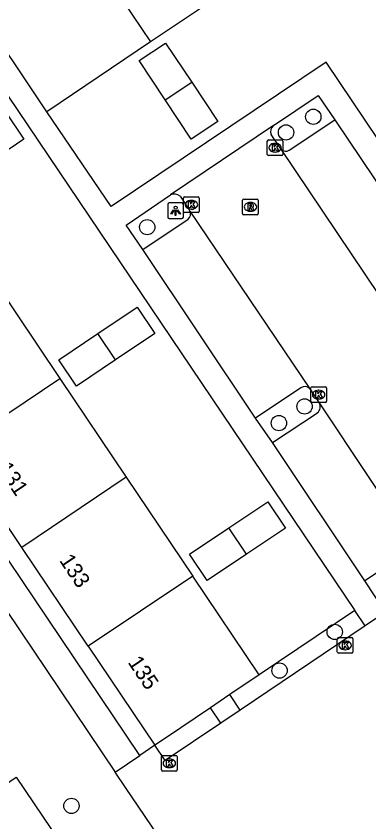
# Model space of a CAD drawing. Extents: x 158797 to 159887, y 384318 to 385255.
# Drawn here: x 159193.3 to 159215.9, y 384585.2 to 384636.8 of the extents above; entities that cross this region are included whole.
import ezdxf

# ---------------------------------------------------------------- set-up
doc = ezdxf.new("R2010")
doc.units = 0
for name, color, linetype in [('IMGEO_Boom', 7, 'Continuous'), ('IMGEO_Groenvoorziening', 7, 'Continuous'), ('IMGEO_Kolk', 7, 'Continuous'), ('IMGEO_Lichtpunt', 7, 'Continuous'), ('IMGEO_Pand', 7, 'Continuous'), ('IMGEO_Pand_nummerreeks', 7, 'Continuous'), ('IMGEO_Parkeervlak_open', 7, 'Continuous'), ('IMGEO_Rijbaan_lokaal_open', 7, 'Continuous'), ('IMGEO_Rioolput', 7, 'Continuous'), ('IMGEO_Voetpad_gesloten', 7, 'Continuous'), ('IMGEO_Voetpad_open', 7, 'Continuous')]:
    doc.layers.add(name, color=color, linetype=linetype)

msp = doc.modelspace()

# ---------------------------------------------------------------- linework, layer by layer
at = {"layer": 'IMGEO_Boom'}
for centre in [(159212.336, 384630.339), (159210.593, 384629.335), (159201.717, 384623.279), (159211.781, 384611.814), (159210.14, 384610.751), (159213.705, 384597.396), (159210.177, 384594.923), (159196.875, 384586.273)]:
    msp.add_circle(centre, 0.489, dxfattribs=at)
at = {"layer": 'IMGEO_Groenvoorziening'}
msp.add_lwpolyline([(159214.996, 384598.764), (159208.877, 384594.644)], dxfattribs=at)
at = {"layer": 'IMGEO_Kolk'}
for p, q in [((159209.397, 384627.93), (159209.397, 384628.782)), ((159209.472, 384628.856), (159210.324, 384628.856)), ((159209.885, 384628.636), (159209.91, 384628.636)), ((159210.398, 384628.782), (159210.398, 384627.93)), ((159209.908, 384628.076), (159209.883, 384628.076)), ((159210.324, 384627.856), (159209.472, 384627.856)), ((159204.046, 384624.284), (159204.046, 384625.136)), ((159204.121, 384625.21), (159204.973, 384625.21)), ((159204.534, 384624.99), (159204.559, 384624.99)), ((159205.047, 384625.136), (159205.047, 384624.284)), ((159204.557, 384624.43), (159204.532, 384624.43)), ((159204.973, 384624.21), (159204.121, 384624.21)), ((159212.181, 384612.145), (159212.181, 384612.997)), ((159212.256, 384613.071), (159213.108, 384613.071)), ((159213.182, 384612.997), (159213.182, 384612.145)), ((159212.669, 384612.851), (159212.694, 384612.851)), ((159213.108, 384612.071), (159212.256, 384612.071)), ((159212.692, 384612.291), (159212.667, 384612.291)), ((159213.948, 384597.035), (159214.8, 384597.035)), ((159213.873, 384596.109), (159213.873, 384596.961)), ((159214.361, 384596.815), (159214.386, 384596.815)), ((159214.874, 384596.961), (159214.874, 384596.109)), ((159214.8, 384596.035), (159213.948, 384596.035)), ((159214.384, 384596.255), (159214.359, 384596.255)), ((159202.632, 384588.57), (159202.632, 384589.422)), ((159202.707, 384589.496), (159203.559, 384589.496)), ((159203.12, 384589.276), (159203.145, 384589.276)), ((159203.633, 384589.422), (159203.633, 384588.57)), ((159203.559, 384588.496), (159202.707, 384588.496)), ((159203.143, 384588.716), (159203.118, 384588.716))]:
    msp.add_line(p, q, dxfattribs=at)
for points in [[(159209.397, 384627.93), (159209.397, 384628.782)], [(159209.472, 384628.856), (159210.324, 384628.856)], [(159209.718, 384628.556), (159209.841, 384628.556), (159209.841, 384628.405), (159209.971, 384628.556), (159210.135, 384628.556), (159209.989, 384628.405), (159210.142, 384628.156), (159209.99, 384628.156), (159209.905, 384628.32), (159209.841, 384628.253), (159209.841, 384628.156), (159209.718, 384628.156), (159209.718, 384628.556)], [(159210.398, 384628.782), (159210.398, 384627.93)], [(159210.324, 384627.856), (159209.472, 384627.856)], [(159204.046, 384624.284), (159204.046, 384625.136)], [(159204.121, 384625.21), (159204.973, 384625.21)], [(159204.367, 384624.91), (159204.49, 384624.91), (159204.49, 384624.759), (159204.62, 384624.91), (159204.784, 384624.91), (159204.638, 384624.759), (159204.791, 384624.51), (159204.639, 384624.51), (159204.554, 384624.674), (159204.49, 384624.607), (159204.49, 384624.51), (159204.367, 384624.51), (159204.367, 384624.91)], [(159205.047, 384625.136), (159205.047, 384624.284)], [(159204.973, 384624.21), (159204.121, 384624.21)], [(159212.181, 384612.145), (159212.181, 384612.997)], [(159212.256, 384613.071), (159213.108, 384613.071)], [(159213.182, 384612.997), (159213.182, 384612.145)], [(159212.502, 384612.771), (159212.625, 384612.771), (159212.625, 384612.62), (159212.755, 384612.771), (159212.919, 384612.771), (159212.773, 384612.62), (159212.926, 384612.371), (159212.774, 384612.371), (159212.689, 384612.535), (159212.625, 384612.468), (159212.625, 384612.371), (159212.502, 384612.371), (159212.502, 384612.771)], [(159213.108, 384612.071), (159212.256, 384612.071)], [(159213.948, 384597.035), (159214.8, 384597.035)], [(159213.873, 384596.109), (159213.873, 384596.961)], [(159214.194, 384596.735), (159214.317, 384596.735), (159214.317, 384596.584), (159214.447, 384596.735), (159214.611, 384596.735), (159214.465, 384596.584), (159214.618, 384596.335), (159214.466, 384596.335), (159214.381, 384596.499), (159214.317, 384596.432), (159214.317, 384596.335), (159214.194, 384596.335), (159214.194, 384596.735)], [(159214.874, 384596.961), (159214.874, 384596.109)], [(159214.8, 384596.035), (159213.948, 384596.035)], [(159202.632, 384588.57), (159202.632, 384589.422)], [(159202.707, 384589.496), (159203.559, 384589.496)], [(159203.633, 384589.422), (159203.633, 384588.57)], [(159202.953, 384589.196), (159203.076, 384589.196), (159203.076, 384589.045), (159203.206, 384589.196), (159203.37, 384589.196), (159203.224, 384589.045), (159203.377, 384588.796), (159203.225, 384588.796), (159203.14, 384588.96), (159203.076, 384588.893), (159203.076, 384588.796), (159202.953, 384588.796), (159202.953, 384589.196)], [(159203.559, 384588.496), (159202.707, 384588.496)]]:
    msp.add_lwpolyline(points, dxfattribs=at)
for centre, start, end in [((159209.474, 384628.78), 91.552, 178.448), ((159209.474, 384628.78), 91.552, 178.448), ((159210.322, 384628.78), 1.552, 88.448), ((159210.322, 384628.78), 1.552, 88.448), ((159209.474, 384627.932), 181.552, 268.448), ((159209.474, 384627.932), 181.552, 268.448), ((159210.322, 384627.932), 271.552, 358.448), ((159210.322, 384627.932), 271.552, 358.448), ((159204.123, 384625.134), 91.552, 178.448), ((159204.123, 384625.134), 91.552, 178.448), ((159204.971, 384625.134), 1.552, 88.448), ((159204.971, 384625.134), 1.552, 88.448), ((159204.123, 384624.286), 181.552, 268.448), ((159204.123, 384624.286), 181.552, 268.448), ((159204.971, 384624.286), 271.552, 358.448), ((159204.971, 384624.286), 271.552, 358.448), ((159212.258, 384612.995), 91.552, 178.448), ((159212.258, 384612.995), 91.552, 178.448), ((159213.106, 384612.995), 1.552, 88.448), ((159213.106, 384612.995), 1.552, 88.448), ((159212.258, 384612.147), 181.552, 268.448), ((159212.258, 384612.147), 181.552, 268.448), ((159213.106, 384612.147), 271.552, 358.448), ((159213.106, 384612.147), 271.552, 358.448), ((159213.95, 384596.959), 91.552, 178.448), ((159213.95, 384596.959), 91.552, 178.448), ((159214.798, 384596.959), 1.552, 88.448), ((159214.798, 384596.959), 1.552, 88.448), ((159213.95, 384596.111), 181.552, 268.448), ((159213.95, 384596.111), 181.552, 268.448), ((159214.798, 384596.111), 271.552, 358.448), ((159214.798, 384596.111), 271.552, 358.448), ((159202.709, 384589.42), 91.552, 178.448), ((159202.709, 384589.42), 91.552, 178.448), ((159203.557, 384589.42), 1.552, 88.448), ((159203.557, 384589.42), 1.552, 88.448), ((159202.709, 384588.572), 181.552, 268.448), ((159202.709, 384588.572), 181.552, 268.448), ((159203.557, 384588.572), 271.552, 358.448), ((159203.557, 384588.572), 271.552, 358.448)]:
    msp.add_arc(centre, 0.0765, start, end, dxfattribs=at)
for centre, major_axis, ratio, start_param, end_param in [((159209.884, 384628.356), (-0.387, 0.002), 0.722429, 4.712389, 7.853982), ((159209.909, 384628.356), (-0.39, 0.002), 0.717154, 1.570796, 4.712389), ((159204.533, 384624.71), (-0.387, 0.002), 0.722429, 4.712389, 7.853982), ((159204.558, 384624.71), (-0.39, 0.002), 0.717154, 1.570796, 4.712389), ((159212.668, 384612.571), (-0.387, 0.002), 0.722429, 4.712389, 7.853982), ((159212.693, 384612.571), (-0.39, 0.002), 0.717154, 1.570796, 4.712389), ((159214.36, 384596.535), (-0.387, 0.002), 0.722429, 4.712389, 7.853982), ((159214.385, 384596.535), (-0.39, 0.002), 0.717154, 1.570796, 4.712389), ((159203.119, 384588.996), (-0.387, 0.002), 0.722429, 4.712389, 7.853982), ((159203.144, 384588.996), (-0.39, 0.002), 0.717154, 1.570796, 4.712389)]:
    msp.add_ellipse(centre, major_axis=major_axis, ratio=ratio, start_param=start_param, end_param=end_param, dxfattribs=at)
at = {"layer": 'IMGEO_Lichtpunt'}
for p, q in [((159203.938, 384624.828), (159203.13, 384624.828)), ((159203.938, 384624.828), (159203.13, 384624.828)), ((159203.036, 384624.733), (159203.036, 384623.926)), ((159203.036, 384624.733), (159203.036, 384623.926)), ((159204.032, 384623.926), (159204.032, 384624.733)), ((159204.032, 384623.926), (159204.032, 384624.733)), ((159203.13, 384623.832), (159203.938, 384623.832)), ((159203.13, 384623.832), (159203.938, 384623.832))]:
    msp.add_line(p, q, dxfattribs=at)
for points in [[(159203.41, 384624.397), (159203.449, 384624.369), (159203.261, 384624.107), (159203.223, 384624.134), (159203.41, 384624.397)], [(159203.512, 384624.349), (159203.559, 384624.349), (159203.559, 384624.027), (159203.512, 384624.027), (159203.512, 384624.349)], [(159203.622, 384624.369), (159203.66, 384624.396), (159203.847, 384624.134), (159203.808, 384624.106), (159203.622, 384624.369)]]:
    msp.add_lwpolyline(points, dxfattribs=at)
msp.add_circle((159203.535, 384624.531), 0.0994, dxfattribs=at)
for centre, start, end in [((159203.13, 384624.733), 90, 180), ((159203.13, 384624.733), 90, 180), ((159203.938, 384624.733), 0, 90), ((159203.938, 384624.733), 0, 90), ((159203.13, 384623.926), 180, 270), ((159203.13, 384623.926), 180, 270), ((159203.938, 384623.926), 270, 0), ((159203.938, 384623.926), 270, 360)]:
    msp.add_arc(centre, 0.0946, start, end, dxfattribs=at)
at = {"layer": 'IMGEO_Pand'}
for points in [[(159195.293, 384630.658), (159190.691, 384637.509), (159197.331, 384641.969)], [(159197.331, 384641.969), (159201.934, 384635.126)], [(159208.576, 384639.594), (159201.934, 384635.126)], [(159201.934, 384635.126), (159195.293, 384630.658)], [(159202.866, 384631.42), (159201.199, 384633.933), (159202.895, 384635.055), (159204.561, 384632.544)], [(159204.561, 384632.544), (159206.226, 384630.032), (159204.532, 384628.908), (159202.866, 384631.42)], [(159202.866, 384631.42), (159204.561, 384632.544)], [(159190.199, 384628.918), (159192.698, 384630.6), (159193.834, 384628.912), (159191.334, 384627.231)], [(159191.879, 384619.926), (159196.129, 384613.605)], [(159198.57, 384616.469), (159201.077, 384618.153), (159202.2, 384616.471), (159199.701, 384614.789)], [(159199.701, 384614.789), (159197.201, 384613.107), (159196.069, 384614.789), (159198.57, 384616.469)], [(159199.701, 384614.789), (159198.57, 384616.469)], [(159189.452, 384609.117), (159196.129, 384613.605)], [(159196.129, 384613.605), (159200.378, 384607.285)], [(159193.701, 384602.796), (159189.452, 384609.117)], [(159200.378, 384607.285), (159193.701, 384602.796)], [(159200.378, 384607.285), (159204.628, 384600.965)], [(159206.933, 384604.049), (159209.435, 384605.721), (159210.565, 384604.034), (159208.062, 384602.359)], [(159208.062, 384602.359), (159205.56, 384600.685), (159204.43, 384602.377), (159206.933, 384604.049)], [(159208.062, 384602.359), (159206.933, 384604.049)], [(159197.95, 384596.475), (159193.701, 384602.796)], [(159204.628, 384600.965), (159197.95, 384596.475)], [(159208.877, 384594.644), (159204.628, 384600.965)], [(159197.95, 384596.475), (159202.203, 384590.149)], [(159208.877, 384594.644), (159207.011, 384593.387)], [(159207.011, 384593.387), (159205.763, 384592.546)], [(159205.763, 384592.546), (159202.885, 384590.608), (159202.203, 384590.149)]]:
    msp.add_lwpolyline(points, dxfattribs=at)
at = {"layer": 'IMGEO_Parkeervlak_open'}
for points in [[(159210.804, 384628.193), (159213.721, 384630.148)], [(159201.442, 384621.858), (159204.327, 384623.794)], [(159211.548, 384613.012), (159208.644, 384611.068)], [(159209.726, 384609.51), (159212.595, 384611.412)], [(159218.552, 384602.596), (159215.624, 384600.655)]]:
    msp.add_lwpolyline(points, dxfattribs=at)
for centre, radius, start, end in [((159210.583, 384628.525), 0.399, 220.4801, 303.6579), ((159204.058, 384624.132), 0.432, 308.5941, 24.6907), ((159211.795, 384612.644), 0.443, 42.7962, 123.8423), ((159212.305, 384611.794), 0.479, 307.208, 31.4651)]:
    msp.add_arc(centre, radius, start, end, dxfattribs=at)
at = {"layer": 'IMGEO_Rijbaan_lokaal_open'}
for points in [[(159209.792, 384629.775), (159203.215, 384625.336)], [(159210.28, 384628.266), (159210.228, 384628.343), (159209.641, 384629.203)], [(159216.571, 384618.899), (159210.28, 384628.266)], [(159203.815, 384625.262), (159204.409, 384624.383)], [(159204.45, 384624.312), (159212.12, 384612.945)], [(159212.168, 384612.883), (159212.714, 384612.044)], [(159212.714, 384612.044), (159219.065, 384602.496)], [(159216.947, 384598.656), (159215.656, 384597.786)], [(159215.656, 384597.786), (159207.663, 384592.398)], [(159207.663, 384592.398), (159206.415, 384591.557)], [(159206.415, 384591.557), (159202.865, 384589.164), (159202.203, 384590.149)], [(159202.203, 384590.149), (159201.24, 384589.496)], [(159199.667, 384588.43), (159201.24, 384589.496)], [(159202.847, 384583.73), (159200.329, 384587.446), (159199.667, 384588.43)]]:
    msp.add_lwpolyline(points, dxfattribs=at)
for centre, radius, start, end in [((159210.083, 384629.392), 0.481, 127.2173, 203.2069), ((159203.461, 384624.862), 0.534, 48.4804, 117.4577), ((159204.075, 384624.143), 0.411, 24.2808, 35.7291), ((159211.711, 384612.579), 0.548, 33.6479, 41.8457)]:
    msp.add_arc(centre, radius, start, end, dxfattribs=at)
at = {"layer": 'IMGEO_Rioolput'}
for p, q in [((159207.818, 384624.15), (159207.818, 384625.002)), ((159207.893, 384625.076), (159208.745, 384625.076)), ((159208.306, 384624.856), (159208.331, 384624.856)), ((159208.819, 384625.002), (159208.819, 384624.15)), ((159208.329, 384624.296), (159208.304, 384624.296)), ((159208.745, 384624.076), (159207.893, 384624.076))]:
    msp.add_line(p, q, dxfattribs=at)
for points in [[(159207.818, 384624.15), (159207.818, 384625.002)], [(159207.893, 384625.076), (159208.745, 384625.076)], [(159208.819, 384625.002), (159208.819, 384624.15)], [(159208.407, 384624.774), (159208.155, 384624.776), (159208.155, 384624.376)], [(159208.155, 384624.376), (159208.279, 384624.376), (159208.279, 384624.538), (159208.29, 384624.538)], [(159208.333, 384624.695), (159208.279, 384624.695), (159208.279, 384624.614)], [(159208.279, 384624.614), (159208.331, 384624.614)], [(159208.337, 384624.509), (159208.408, 384624.376), (159208.548, 384624.376), (159208.483, 384624.502)], [(159208.745, 384624.076), (159207.893, 384624.076)]]:
    msp.add_lwpolyline(points, dxfattribs=at)
for centre, radius, start, end in [((159207.895, 384625), 0.0765, 91.552, 178.448), ((159207.895, 384625), 0.0765, 91.552, 178.448), ((159208.743, 384625), 0.0765, 1.552, 88.448), ((159208.743, 384625), 0.0765, 1.552, 88.448), ((159208.289, 384624.485), 0.0533, 26.0293, 88.6989), ((159208.315, 384624.803), 0.19, 274.7715, 282.9687), ((159208.339, 384624.599), 0.0964, 77.0061, 93.1865), ((159208.353, 384624.656), 0.0378, 276.6634, 79.6772), ((159208.406, 384624.664), 0.109, 350.3612, 89.416), ((159208.404, 384624.664), 0.112, 277.5842, 350.9817), ((159208.388, 384624.449), 0.108, 29.5134, 73.7905), ((159207.895, 384624.152), 0.0765, 181.552, 268.448), ((159207.895, 384624.152), 0.0765, 181.552, 268.448), ((159208.743, 384624.152), 0.0765, 271.552, 358.448), ((159208.743, 384624.152), 0.0765, 271.552, 358.448)]:
    msp.add_arc(centre, radius, start, end, dxfattribs=at)
for centre, major_axis, ratio, start_param, end_param in [((159208.305, 384624.576), (-0.387, 0.002), 0.722429, 4.712389, 7.853982), ((159208.33, 384624.576), (-0.39, 0.002), 0.717154, 1.570796, 4.712389)]:
    msp.add_ellipse(centre, major_axis=major_axis, ratio=ratio, start_param=start_param, end_param=end_param, dxfattribs=at)
at = {"layer": 'IMGEO_Voetpad_gesloten'}
msp.add_lwpolyline([(159139.375, 384579.667), (159141.123, 384576.932), (159150.625, 384583.433), (159151.747, 384581.759), (159165.041, 384590.724), (159170.605, 384582.437), (159174.689, 384585.159), (159179.297, 384578.512), (159193.347, 384588.107), (159197.808, 384581.483), (159198.988, 384582.307), (159199.249, 384581.925), (159200.917, 384582.98), (159201.158, 384582.618), (159202.847, 384583.73)], dxfattribs=at)
at = {"layer": 'IMGEO_Voetpad_open'}
for points in [[(159189.5, 384636.563), (159214.996, 384598.764)], [(159229.995, 384608.782), (159213.158, 384633.835), (159199.409, 384624.591), (159195.293, 384630.658)], [(159209.792, 384629.775), (159212.653, 384631.694), (159213.721, 384630.148)], [(159213.721, 384630.148), (159219.57, 384621.416)], [(159201.24, 384589.496), (159185.263, 384613.249), (159175.767, 384627.444), (159176.706, 384628.077)], [(159201.442, 384621.858), (159200.364, 384623.414), (159203.215, 384625.336)], [(159208.644, 384611.068), (159201.442, 384621.858)], [(159209.726, 384609.51), (159208.644, 384611.068)], [(159139.375, 384579.667), (159149.937, 384586.778), (159184.844, 384610.474), (159199.667, 384588.43)], [(159215.624, 384600.655), (159209.726, 384609.51)], [(159216.947, 384598.656), (159215.624, 384600.655)], [(159215.656, 384597.786), (159214.996, 384598.764)], [(159207.663, 384592.398), (159207.011, 384593.387)], [(159206.415, 384591.557), (159205.763, 384592.546)]]:
    msp.add_lwpolyline(points, dxfattribs=at)

# ---------------------------------------------------------------- texts
at = {"layer": 'IMGEO_Pand_nummerreeks'}
for s, p in [('131', (159192.108, 384607.855)), ('133', (159196.066, 384601.967)), ('135', (159200.447, 384595.45))]:
    msp.add_text(s, height=1, rotation=303.9132, dxfattribs=at).set_placement(p)

doc.saveas('drawing.dxf')
